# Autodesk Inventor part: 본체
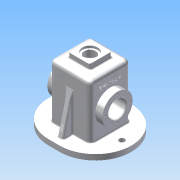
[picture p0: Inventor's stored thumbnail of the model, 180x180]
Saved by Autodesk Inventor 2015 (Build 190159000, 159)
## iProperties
Created: 2017-07
Part Number: 본체
Material: 알루미늄 6061
Document SubType Name: Modeling
Designer: Administrator
Density: 2.7 g/cm^3
Appearance: 알루미늄 - 평지
Mass: 1003.2 g
Surface Area: 1095.96 cm^2
Volume: 371.556 cm^3
Author: Administrator
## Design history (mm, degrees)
sketch "스케치2"
  geometry: L1 (37, -37)-(-37, -37); L2 (-37, -37)-(-37, 37); L3 (-37, 37)-(37, 37); L4 (37, 37)-(37, -37); L5 (37, -37)-(-37, 37); L6 (-37, -37)-(37, 37); 1 further point
  constraints: 12 end point, 2 midpoint, 2 parallel, 1 horizontal, 1 perpendicular
  dimensions: "d2" = 74 distance between parallel lines of L2 L4; "d3" = 74 distance between parallel lines of L3 L1
extrude "돌출1" new body sketch "스케치2" distance "d4" = 110; taper "d5" = 0 deg
fillet "모깎기1" dims "d6" = 8
sketch "스케치3"
  geometry: L1 (74, 0)-(0, 0) reference; L2 (74, 0)-(74, 102) reference; C1 r 27.5 at (37, 55); 1 further point
  constraints: 1 centre point
  dimensions: "d7" = 55 distance from line of L1 C1.centre; "d8" = 37 distance from line of L2 C1.centre; "d11" = 55 diameter of C1
extrude "돌출2" join sketch "스케치3" distance "d12" = 13; taper "d13" = 0 deg
sketch "스케치4"
  geometry: L1 (74, 0)-(0, 0) reference; C1 r 27.5 at (37, 55); 2 further points
  constraints: 1 centre point, 1 midpoint, 1 vertical alignment
  dimensions: "d14" = 55 diameter of C1; "d15" = 55 distance from line of L1 C1.centre
extrude "돌출3" join sketch "스케치4" distance "d16" = 13; taper "d17" = 0 deg
sketch "스케치5"
  geometry: L1 (29, 110)-(-29, 110) reference; L2 (37, 0)-(37, 102) reference; L3 (-37, 0)-(37, 0) reference; L4 (-37, 0)-(-37, 102) reference; L5 (29, 105)-(-29, 105); L6 (-32, 102)-(-32, 0); L7 (32, 0)-(32, 102); L8 (-32, 0)-(32, 0); A1 r 8 centre (-29, 102) between (-29, 110) and (-37, 102) reference; A2 r 8 centre (29, 102) between (37, 102) and (29, 110) reference; A3 r 3 centre (29, 102) between (32, 102) and (29, 105); A4 r 3 centre (-29, 102) between (-29, 105) and (-32, 102); 1 further point
  constraints: 8 end point, 4 point on circle, 2 centre point, 2 point on line, 1 collinear, 1 tangent, 2 other
  dimensions: "d18" = 5 distance between parallel lines of L2 L7; "d19" = 64 distance between parallel lines of L7 L6
extrude "돌출4" cut sketch "스케치5" stored distance "d20" = 64; taper "d21" = 0 deg
sketch "스케치6"
  geometry: L1 (32, 0)-(-32, 0) reference; L2 (-25, 55)-(-32, 55); L3 (-32, 0)-(-32, 102) reference; L4 (-25, 75.5)-(-25, 55); L5 (-25, 75.5)-(-32, 82.5); L6 (-32, 82.5)-(-32, 55); 1 further point
  constraints: 8 end point, 1 collinear, 1 parallel, 1 point on line
  dimensions: "d22" = 55 distance between parallel lines of L1 L2; "d24" = 7 distance between parallel lines of L3 L4; "d26" = 135 deg angle of L4 L5; "d90" = 27.5 distance of L2.end L5.end
revolve "회전1" sketch "스케치6" stored, may be unused: angle "d28" = 90 deg
sketch "스케치7"
  geometry: C1 r 16 at (0, 0); 2 further points
  constraints: 1 centre point, 1 coincident
  dimensions: "d30" = 32 diameter of C1
extrude "돌출5" cut sketch "스케치7" stored distance "d31" = 40; taper "d32" = 0 deg
sketch "스케치8"
  geometry: C1 r 16 at (0, 0) reference; 2 further points
  constraints: 1 vertical alignment
  dimensions: "d33" = 22.5 distance of C1.centre point (0, 22.5)
hole "구멍1" sketch "스케치8" at (0, 22.5) diameter "d34" = 3.242; stored, may be unused: countersink angle "d38" = 90 deg, drill point angle "d40" = 118 deg; dims "d35" = 8, "d36" = 4, "d37" = 2, "d39" = 10
sketch "스케치9"
  geometry: L1 (-20, 20)-(20, 20); L2 (20, 20)-(20, -20); L3 (20, -20)-(-20, -20); L4 (-20, -20)-(-20, 20); L5 (-20, 20)-(20, -20); L6 (20, 20)-(-20, -20); 1 further point
  constraints: 12 end point, 2 midpoint, 2 parallel, 1 horizontal, 1 perpendicular
  dimensions: "d44" = 40 distance between parallel lines of L2 L4; "d45" = 40 distance between parallel lines of L3 L1
extrude "돌출6" join sketch "스케치9" distance "d46" = 10; taper "d47" = 0 deg
feature "면 기울기1" dims angle "d48" = 5 deg
feature "면 기울기2" dims angle "d49" = 5 deg
sketch "스케치10"
  geometry: C1 r 14 at (0, 0); 1 further point
  constraints: 1 centre point, 1 coincident
  dimensions: "d100" = 28 diameter of C1
extrude "돌출7" cut sketch "스케치10" distance "d53" = 4; taper "d54" = 0 deg
sketch "스케치11"
  geometry: C1 r 14 at (0, 0) reference; C2 r 10.5 at (0, 0)
  constraints: 1 centre point, 1 coincident
  dimensions: "d55" = 21 diameter of C2
extrude "돌출8" cut sketch "스케치11" distance "d56" = 50; taper "d57" = 0 deg
sketch "스케치12"
  geometry: L1 (-29, -37)-(29, -37) reference; L2 (29, 37)-(-29, 37) reference; L3 (-37, 37)-(-37, -37) reference; L4 (37, -37)-(37, 37) reference; L5 (75, -65)-(-75, -65); L6 (-75, -65)-(-75, 65); L7 (-75, 65)-(75, 65); L8 (75, 65)-(75, -65); L9 (75, -65)-(-75, 65); L10 (-75, -65)-(75, 65); 1 further point
  constraints: 12 end point, 2 midpoint, 2 parallel, 1 horizontal, 1 perpendicular
  dimensions: "d58" = 150 distance between parallel lines of L8 L6; "d59" = 130 distance between parallel lines of L7 L5
extrude "돌출9" join sketch "스케치12" distance "d60" = 10; taper "d61" = 0 deg
sketch "스케치13"
  geometry: L1 (-32, 32)-(32, 32); L2 (32, 32)-(32, -32); L3 (32, -32)-(-32, -32); L4 (-32, -32)-(-32, 32); L5 (-32, 32)-(32, -32); L6 (32, 32)-(-32, -32); 1 further point
  constraints: 12 end point, 2 midpoint, 2 parallel, 1 horizontal, 1 perpendicular
  dimensions: "d62" = 64 distance between parallel lines of L4 L2; "d63" = 64 distance between parallel lines of L3 L1
extrude "돌출10" cut sketch "스케치13" distance "d64" = 10; taper "d65" = 0 deg
sketch "스케치14"
  geometry: C1 r 5 at (58, 0); 1 further point
  constraints: 1 centre point, 1 horizontal alignment
  dimensions: "d67" = 10 diameter of C1; "d68" = 58 distance of point (0, 0) C1.centre
extrude "돌출11" cut sketch "스케치14" distance "d69" = 10; taper "d70" = 0 deg
fillet "모깎기2" dims "d74" = 3
fillet "모깎기3" dims "d75" = 3
fillet "모깎기4" dims "d76" = 8
sketch "스케치15"
  geometry: L1 (10, 55)-(82.194, 37); L2 (10, -65)-(10, 65) reference; L3 (10, 37)-(102, 37) reference; L4 (82.194, 37)-(10, 37); L5 (10, 55)-(10, 37); 2 further points
  constraints: 6 end point, 3 point on line, 1 collinear
  dimensions: "d80" = 104 deg angle of L2 L1; "d81" = 90 deg angle of L4 L2; "d82" = 4.79149 distance from line of L3.end L1
extrude "돌출12" join sketch "스케치15" stored distance "d83" = 10; taper "d84" = 0 deg
fillet "모깎기6" dims "d85" = 3
fillet "모깎기7" dims "d86" = 3
chamfer "모따기1" distance "d87" = 1; stored, may be unused: second distance "d88" = 2, angle "d89" = 45 deg
sketch "스케치16"
  geometry: L1 (12, 18)-(46, 18) reference; L2 (66, -89)-(66, 0) reference; 2 further points
  constraints: 1 other
  dimensions: "d91" = 30 distance from line of point (29, -12) L1; "d92" = 37 distance from line of L2 point (29, -12)
feature "엠보싱1" sketch "스케치16" dims "d93" = 0.5, "d94" = 0
fillet "모깎기8" dims "d95" = 3
fillet "모깎기9" dims "d96" = 65
fillet "모깎기10" dims "d97" = 65
fillet "모깎기11" dims "d98" = 65
fillet "모깎기12" dims "d99" = 65
fillet "모깎기13" dims "d101" = 0.3
fillet "모깎기14" dims "d102" = 0.3
fillet "모깎기15" dims "d103" = 0.3
node "솔리드1"
mirror "대칭1"
pattern_circular "원형 패턴1" dims angle "d42" = 360 deg
mirror "대칭2"
pattern_linear "직사각형 패턴1" dims "d73" = 116
mirror "대칭3"
node "투영된 루프1"
